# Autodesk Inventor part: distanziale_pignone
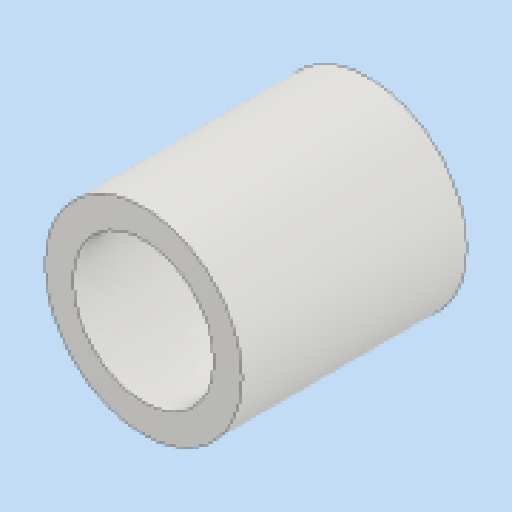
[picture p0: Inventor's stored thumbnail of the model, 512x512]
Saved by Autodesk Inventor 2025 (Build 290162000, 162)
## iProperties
Created: 2026-05
Part Number: distanziale_pignone
Material: Bronzo, Stagno dolce
Document SubType Name: Modeling
Designer: R5800u
Density: 8.874 g/cm^3
Appearance: Acciaio
Author: R5800u
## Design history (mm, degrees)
sketch "Schizzo1"
  geometry: C1 r 12.5 at (0, 0); C2 r 17.5 at (0, 0); 1 further point
  constraints: 2 centre point, 1 coincident
  dimensions: "d0" = 25 diameter of C1; "d1" = 5 radial gap between concentric circles of C1 C2
extrude "Estrusione1" new body sketch "Schizzo1" distance "d2" = 40; taper "d3" = 0 deg
node "Solido1"
